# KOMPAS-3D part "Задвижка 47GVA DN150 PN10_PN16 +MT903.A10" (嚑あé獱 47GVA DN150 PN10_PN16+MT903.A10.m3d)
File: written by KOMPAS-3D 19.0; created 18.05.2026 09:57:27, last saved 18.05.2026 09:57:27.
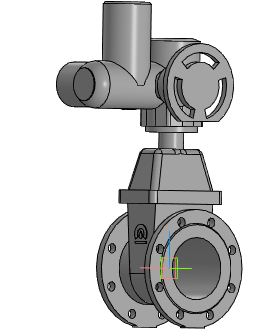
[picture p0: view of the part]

Document properties: Автор: Энергия; Полное имя файла: ..\Задвижка 47GVA DN50_DN1000+MT903.A\Задвижка 47GVA DN150 PN10_PN16+MT903.A10.a3d

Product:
- Part/product: Задвижка 47GVA DN150 PN10_PN16 +MT903.A10
    Масса: 134.552
  - Body: Электропривод МТ903.А10 без блока управления
      Масса: 77.2715
  - Body: Задвижка 47GVA DN150 PN10_PN16 без исполнит. мех.
      Масса: 57.2801

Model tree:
1. Операция без истории:1
2. Операция без истории:2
